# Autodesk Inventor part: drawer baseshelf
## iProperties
Created: 2005-05
Part Number: drawer baseshelf
Material: mdf
Document SubType Name: Modeling
Designer: a.campbell
Manufacturer: Standard
Standards Organization: Custom
Author: a.campbell
Comments: machine to detail
length: 394
thickness: 9
width: 278
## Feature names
1. Extrusion1
